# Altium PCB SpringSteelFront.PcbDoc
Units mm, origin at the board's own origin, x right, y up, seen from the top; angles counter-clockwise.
Board outline 220 x 160 mm, 2 copper layers (Top Layer, Bottom Layer); 0 components, 0 nets, 48 pads, 0 vias.
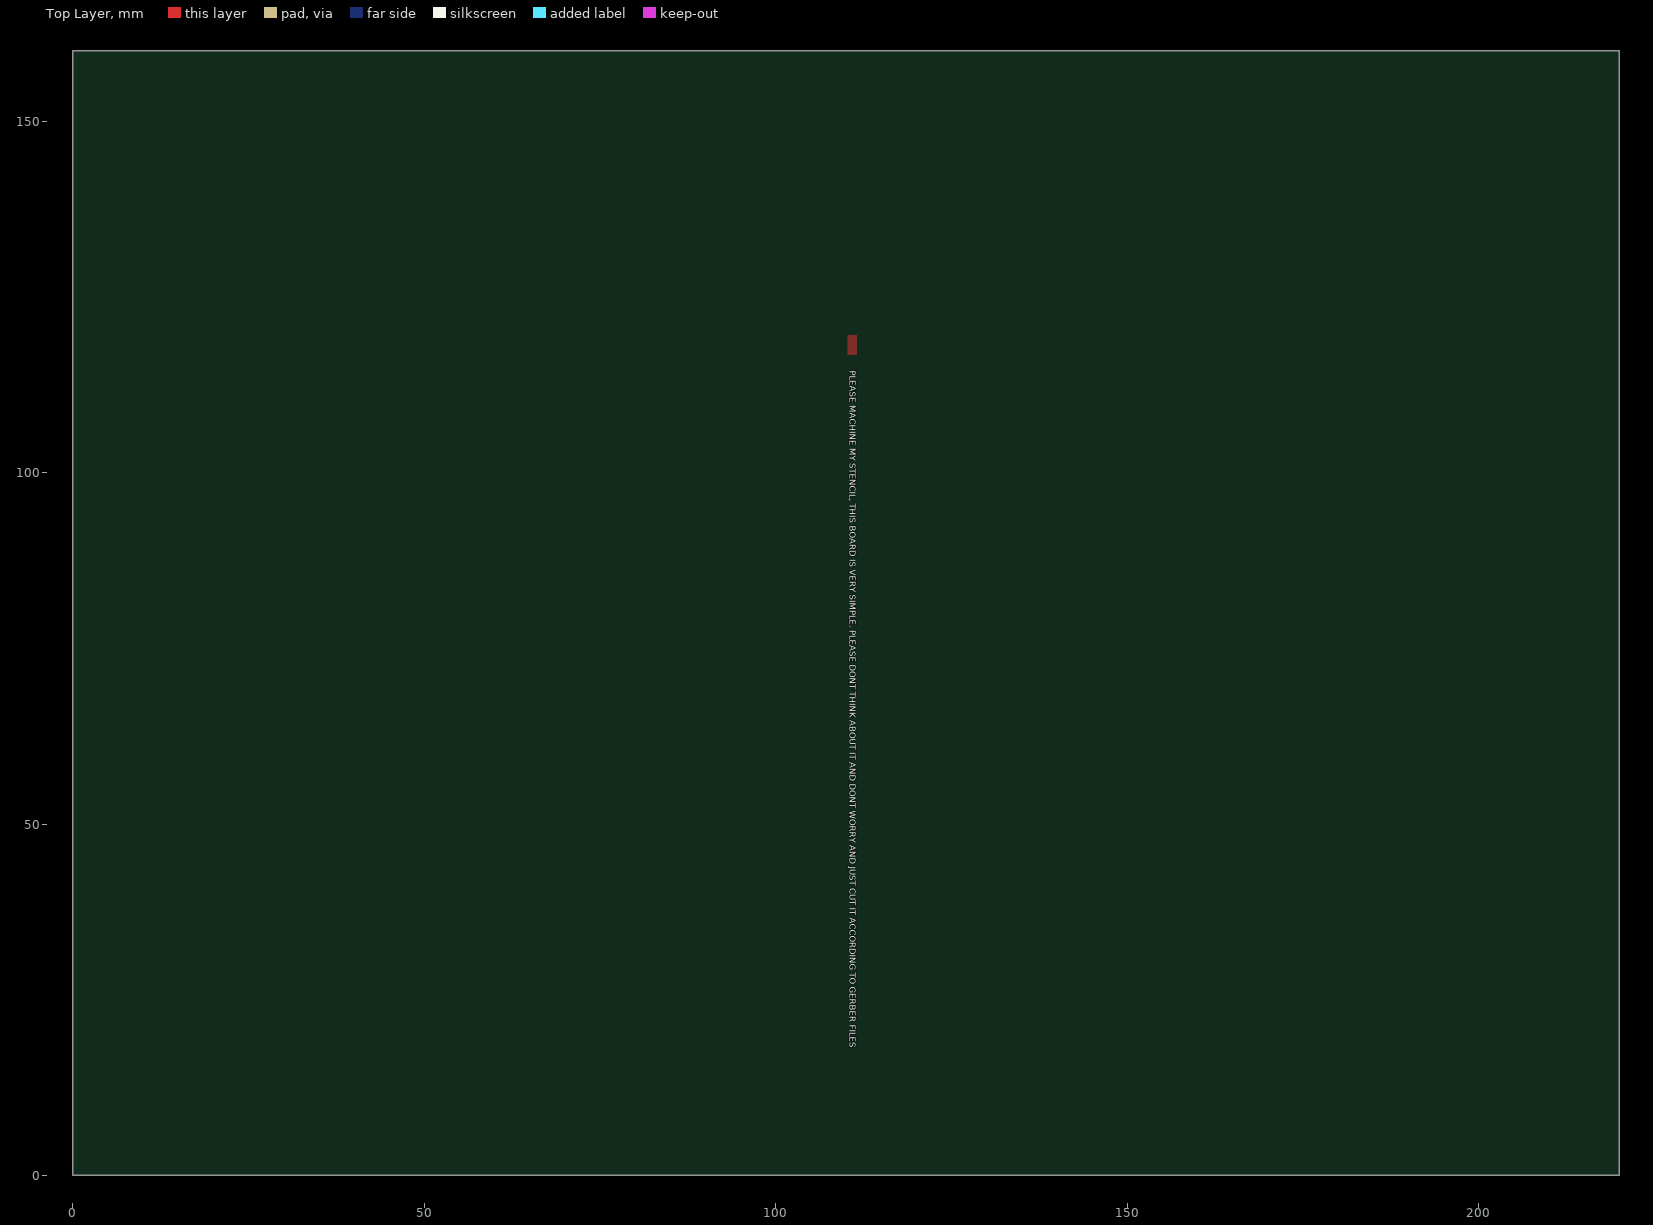
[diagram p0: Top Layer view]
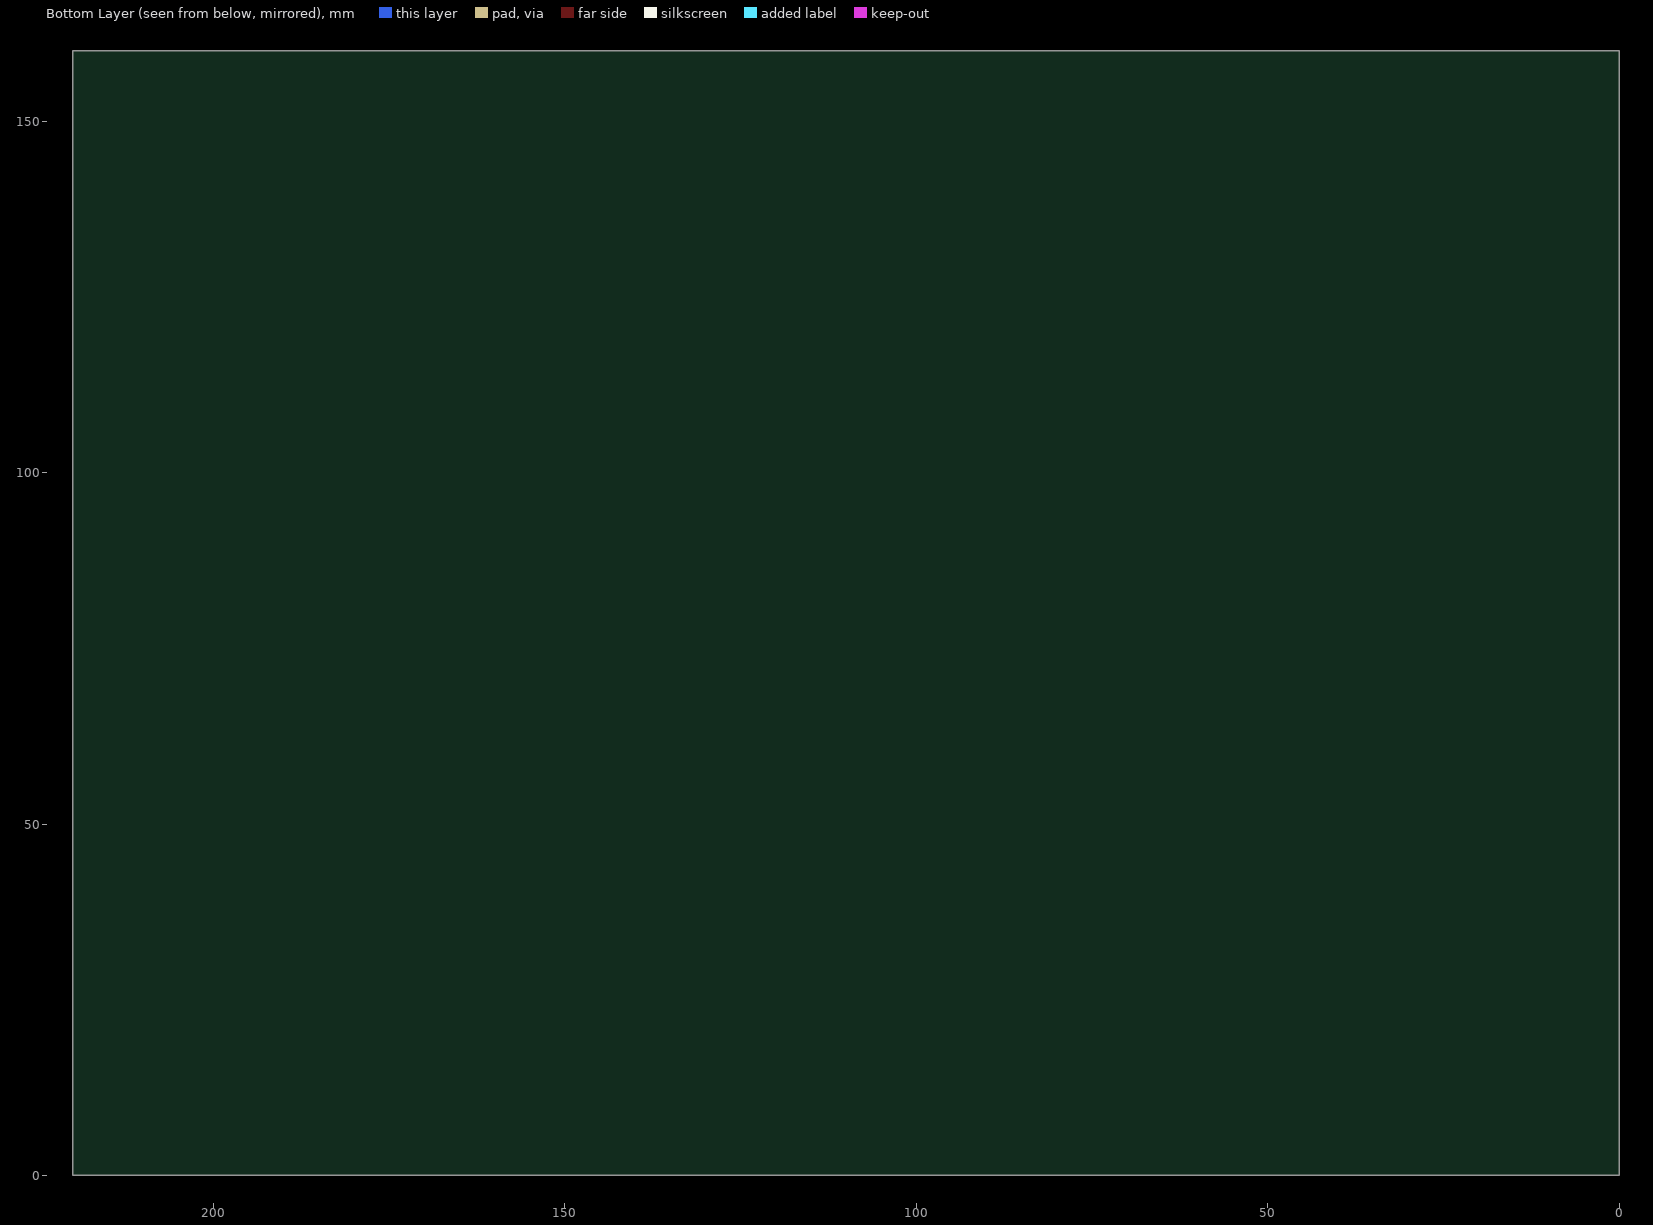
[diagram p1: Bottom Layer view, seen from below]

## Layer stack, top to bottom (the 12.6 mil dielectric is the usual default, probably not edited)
Top Solder: solder mask 0.0102, Solder Resist, Dk 3.5
Top Layer: signal copper 0.0356
Dielectric 1: dielectric 0.32, FR-4, Dk 4.8
Bottom Layer: signal copper 0.0356
Bottom Solder: solder mask 0.0102, Solder Resist, Dk 3.5

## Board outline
220,0 220,160 0,160 0,0

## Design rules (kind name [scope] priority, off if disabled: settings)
Clearance [All] p1: gap=0.254 ignorepadtopadclearanceinfootprint=FALSE except(0: Arc-Hole Track-Hole SMDPad-Hole THPad-Hole Via-Hole Fill-Hole Poly-Hole Region-Hole Text-Hole)
PolygonConnect [All] p1: connectstyle=Relief reliefconductorwidth=0.254 reliefentries=4 polygonreliefangle="90 Angle" airgapwidth=0.254
RoutingVias [All] p1: holewidth=0.711 width=1.27 viastyle="Through Hole" minholewidth=0.711 minwidth=1.27 maxholewidth=0.711 maxwidth=1.27
SolderMaskExpansion [All] p1: expansion=0.102 istentingtop=FALSE
Width [All] p1: maxlimit=0.254 minlimit=0.254 preferedwidth=0.254
30 further rules are at their usual default settings.

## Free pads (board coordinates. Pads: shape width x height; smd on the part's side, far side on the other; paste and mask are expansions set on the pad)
  round 3 on Top Paste: 1(9.353,8.874) 1(9.353,18.465) 1(9.353,47.874) 1(9.353,57.465) 1(9.353,86.874) 1(9.353,96.465) 1(9.353,125.874) 1(9.353,135.465) 1(102.647,8.874) 1(102.647,18.465) 1(102.647,47.874) 1(102.647,57.465) 1(102.647,86.874) 1(102.647,96.465) 1(102.647,125.874) 1(102.647,135.465) 1(118.353,8.874) 1(118.353,18.465) 1(118.353,47.874) 1(118.353,57.465) 1(118.353,86.874) 1(118.353,96.465) 1(118.353,125.874) 1(118.353,135.465) 1(211.647,8.874) 1(211.647,18.465) 1(211.647,47.874) 1(211.647,57.465) 1(211.647,86.874) 1(211.647,96.465) 1(211.647,125.874) 1(211.647,135.465)
  round 8 on Top Paste: 1(15.5,13.187) 1(15.5,52.187) 1(15.5,91.187) 1(15.5,130.187) 1(96.5,13.187) 1(96.5,52.187) 1(96.5,91.187) 1(96.5,130.187) 1(124.5,13.187) 1(124.5,52.187) 1(124.5,91.187) 1(124.5,130.187) 1(205.5,13.187) 1(205.5,52.187) 1(205.5,91.187) 1(205.5,130.187)

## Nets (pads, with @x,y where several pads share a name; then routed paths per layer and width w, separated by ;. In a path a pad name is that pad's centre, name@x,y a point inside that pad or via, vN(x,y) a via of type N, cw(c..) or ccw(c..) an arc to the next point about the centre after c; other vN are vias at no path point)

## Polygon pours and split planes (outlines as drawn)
no net on Top Paste "NONET_L-01_P-001" (solid): 115,119 115,155 215,155 215,119 217,119 217,157 113,157 113,119
no net on Top Paste "NONET_L-01_P-001" (solid): 120,121 125,121 125,119 120,119
no net on Top Paste "NONET_L-01_P-001" (solid): 130,121 135,121 135,119 130,119
no net on Top Paste "NONET_L-01_P-001" (solid): 140,119 140,121 145,121 145,119
no net on Top Paste "NONET_L-01_P-001" (solid): 150,119 150,121 155,121 155,119
no net on Top Paste "NONET_L-01_P-001" (solid): 160,119 160,121 165,121 165,119
no net on Top Paste "NONET_L-01_P-001" (solid): 170,119 170,121 175,121 175,119
no net on Top Paste "NONET_L-01_P-001" (solid): 180,121 185,121 185,119 180,119
no net on Top Paste "NONET_L-01_P-001" (solid): 190,121 190,119 195,119 195,121
no net on Top Paste "NONET_L-01_P-001" (solid): 200,119 200,121 205,121 205,119
no net on Top Paste "NONET_L-01_P-001" (solid): 210,119 210,121 213,121 213,119
no net on Top Paste "NONET_L-01_P-001" (solid): 115,80 115,116 215,116 215,80 217,80 217,118 113,118 113,80
no net on Top Paste "NONET_L-01_P-001" (solid): 120,82 125,82 125,80 120,80
no net on Top Paste "NONET_L-01_P-001" (solid): 130,82 135,82 135,80 130,80
no net on Top Paste "NONET_L-01_P-001" (solid): 140,80 140,82 145,82 145,80
no net on Top Paste "NONET_L-01_P-001" (solid): 150,80 150,82 155,82 155,80
no net on Top Paste "NONET_L-01_P-001" (solid): 160,80 160,82 165,82 165,80
no net on Top Paste "NONET_L-01_P-001" (solid): 170,80 170,82 175,82 175,80
no net on Top Paste "NONET_L-01_P-001" (solid): 180,82 185,82 185,80 180,80
no net on Top Paste "NONET_L-01_P-001" (solid): 190,82 190,80 195,80 195,82
no net on Top Paste "NONET_L-01_P-001" (solid): 200,80 200,82 205,82 205,80
no net on Top Paste "NONET_L-01_P-001" (solid): 210,80 210,82 213,82 213,80
no net on Top Paste "NONET_L-01_P-001" (solid): 115,41 115,77 215,77 215,41 217,41 217,79 113,79 113,41
no net on Top Paste "NONET_L-01_P-001" (solid): 120,43 125,43 125,41 120,41
no net on Top Paste "NONET_L-01_P-001" (solid): 130,43 135,43 135,41 130,41
no net on Top Paste "NONET_L-01_P-001" (solid): 140,41 140,43 145,43 145,41
no net on Top Paste "NONET_L-01_P-001" (solid): 150,41 150,43 155,43 155,41
no net on Top Paste "NONET_L-01_P-001" (solid): 160,41 160,43 165,43 165,41
no net on Top Paste "NONET_L-01_P-001" (solid): 170,41 170,43 175,43 175,41
no net on Top Paste "NONET_L-01_P-001" (solid): 180,43 185,43 185,41 180,41
no net on Top Paste "NONET_L-01_P-001" (solid): 190,43 190,41 195,41 195,43
no net on Top Paste "NONET_L-01_P-001" (solid): 200,41 200,43 205,43 205,41
no net on Top Paste "NONET_L-01_P-001" (solid): 210,41 210,43 213,43 213,41
no net on Top Paste "NONET_L-01_P-001" (solid): 115,2 115,38 215,38 215,2 217,2 217,40 113,40 113,2
no net on Top Paste "NONET_L-01_P-001" (solid): 120,4 125,4 125,2 120,2
no net on Top Paste "NONET_L-01_P-001" (solid): 130,4 135,4 135,2 130,2
no net on Top Paste "NONET_L-01_P-001" (solid): 140,2 140,4 145,4 145,2
no net on Top Paste "NONET_L-01_P-001" (solid): 150,2 150,4 155,4 155,2
no net on Top Paste "NONET_L-01_P-001" (solid): 160,2 160,4 165,4 165,2
no net on Top Paste "NONET_L-01_P-001" (solid): 170,2 170,4 175,4 175,2
no net on Top Paste "NONET_L-01_P-001" (solid): 180,4 185,4 185,2 180,2
no net on Top Paste "NONET_L-01_P-001" (solid): 190,4 190,2 195,2 195,4
no net on Top Paste "NONET_L-01_P-001" (solid): 200,2 200,4 205,4 205,2
no net on Top Paste "NONET_L-01_P-001" (solid): 210,2 210,4 213,4 213,2
no net on Top Paste "NONET_L-01_P-001" (solid): 6,119 6,155 106,155 106,119 108,119 108,157 4,157 4,119
no net on Top Paste "NONET_L-01_P-001" (solid): 11,121 16,121 16,119 11,119
no net on Top Paste "NONET_L-01_P-001" (solid): 21,121 26,121 26,119 21,119
no net on Top Paste "NONET_L-01_P-001" (solid): 31,119 31,121 36,121 36,119
no net on Top Paste "NONET_L-01_P-001" (solid): 41,119 41,121 46,121 46,119
no net on Top Paste "NONET_L-01_P-001" (solid): 51,119 51,121 56,121 56,119
no net on Top Paste "NONET_L-01_P-001" (solid): 61,119 61,121 66,121 66,119
no net on Top Paste "NONET_L-01_P-001" (solid): 71,121 76,121 76,119 71,119
no net on Top Paste "NONET_L-01_P-001" (solid): 81,121 81,119 86,119 86,121
no net on Top Paste "NONET_L-01_P-001" (solid): 91,119 91,121 96,121 96,119
no net on Top Paste "NONET_L-01_P-001" (solid): 101,119 101,121 104,121 104,119
no net on Top Paste "NONET_L-01_P-001" (solid): 6,80 6,116 106,116 106,80 108,80 108,118 4,118 4,80
no net on Top Paste "NONET_L-01_P-001" (solid): 11,82 16,82 16,80 11,80
no net on Top Paste "NONET_L-01_P-001" (solid): 21,82 26,82 26,80 21,80
no net on Top Paste "NONET_L-01_P-001" (solid): 31,80 31,82 36,82 36,80
no net on Top Paste "NONET_L-01_P-001" (solid): 41,80 41,82 46,82 46,80
no net on Top Paste "NONET_L-01_P-001" (solid): 51,80 51,82 56,82 56,80
no net on Top Paste "NONET_L-01_P-001" (solid): 61,80 61,82 66,82 66,80
no net on Top Paste "NONET_L-01_P-001" (solid): 71,82 76,82 76,80 71,80
no net on Top Paste "NONET_L-01_P-001" (solid): 81,82 81,80 86,80 86,82
no net on Top Paste "NONET_L-01_P-001" (solid): 91,80 91,82 96,82 96,80
no net on Top Paste "NONET_L-01_P-001" (solid): 101,80 101,82 104,82 104,80
no net on Top Paste "NONET_L-01_P-001" (solid): 6,41 6,77 106,77 106,41 108,41 108,79 4,79 4,41
no net on Top Paste "NONET_L-01_P-001" (solid): 11,43 16,43 16,41 11,41
no net on Top Paste "NONET_L-01_P-001" (solid): 21,43 26,43 26,41 21,41
no net on Top Paste "NONET_L-01_P-001" (solid): 31,41 31,43 36,43 36,41
no net on Top Paste "NONET_L-01_P-001" (solid): 41,41 41,43 46,43 46,41
no net on Top Paste "NONET_L-01_P-001" (solid): 51,41 51,43 56,43 56,41
no net on Top Paste "NONET_L-01_P-001" (solid): 61,41 61,43 66,43 66,41
no net on Top Paste "NONET_L-01_P-001" (solid): 71,43 76,43 76,41 71,41
no net on Top Paste "NONET_L-01_P-001" (solid): 81,43 81,41 86,41 86,43
no net on Top Paste "NONET_L-01_P-001" (solid): 91,41 91,43 96,43 96,41
no net on Top Paste "NONET_L-01_P-001" (solid): 101,41 101,43 104,43 104,41
no net on Top Paste "NONET_L-01_P-001" (solid): 101,2 101,4 104,4 104,2
no net on Top Paste "NONET_L-01_P-001" (solid): 91,2 91,4 96,4 96,2
no net on Top Paste "NONET_L-01_P-001" (solid): 81,4 81,2 86,2 86,4
no net on Top Paste "NONET_L-01_P-001" (solid): 71,4 76,4 76,2 71,2
no net on Top Paste "NONET_L-01_P-001" (solid): 61,2 61,4 66,4 66,2
no net on Top Paste "NONET_L-01_P-001" (solid): 51,2 51,4 56,4 56,2
no net on Top Paste "NONET_L-01_P-001" (solid): 41,2 41,4 46,4 46,2
no net on Top Paste "NONET_L-01_P-001" (solid): 31,2 31,4 36,4 36,2
no net on Top Paste "NONET_L-01_P-001" (solid): 21,4 26,4 26,2 21,2
no net on Top Paste "NONET_L-01_P-001" (solid): 11,4 16,4 16,2 11,2
no net on Top Paste "NONET_L-01_P-001" (solid): 6,2 6,38 106,38 106,2 108,2 108,40 4,40 4,2
no net on Top Solder "NONET_L-01_P-001" (solid): 110,120 110,116 112,116 112,120
no net on Top Layer "NONET_L-01_P-001" (solid, pour order 1): 110.25,119.5 111.5,119.5 111.5,116.75 110.25,116.75

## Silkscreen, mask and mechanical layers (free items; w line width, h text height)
Top Overlay:
  text "PLEASE MACHINE MY STENCIL, THIS BOARD IS VERY SIMPLE. PLEASE DONT THINK ABOUT IT AND DONT WORRY AND JUST CUT IT ACCORDING TO GERBER FILES" at 110.19,114.5 h1.5 r270
Top Paste:
  drawing of 16 lines, arcs and shapes, not listed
